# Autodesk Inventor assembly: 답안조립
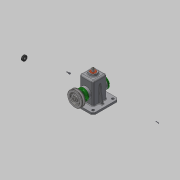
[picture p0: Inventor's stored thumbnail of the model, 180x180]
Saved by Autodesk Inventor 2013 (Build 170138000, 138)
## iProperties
Created: 2016-02
Part Number: 답안조립
Document SubType Name: Assembly
Designer: dgall
Author: dgall
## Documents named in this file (16)
- C:\Users\dgall\Desktop\460211V1003\답안조립.iam
- C:\Users\dgall\Desktop\460211V1003\V벨트풀리.ipt
- C:\Users\dgall\Desktop\460211V1003\고정핀 1.2 x 10.ipt
- C:\Users\dgall\Desktop\460211V1003\뒤커버.ipt
- C:\Users\dgall\Desktop\460211V1003\링크.ipt
- C:\Users\dgall\Desktop\460211V1003\멈춤나사 M3x8.ipt
- C:\Users\dgall\Desktop\460211V1003\베어링 12 x 32 x 10.ipt
- C:\Users\dgall\Desktop\460211V1003\본체.ipt
- C:\Users\dgall\Desktop\460211V1003\볼트 M4 x 12.ipt
- C:\Users\dgall\Desktop\460211V1003\부시.ipt
- C:\Users\dgall\Desktop\460211V1003\슬라이드.ipt
- C:\Users\dgall\Desktop\460211V1003\앞커버.ipt
- C:\Users\dgall\Desktop\460211V1003\오일실 12 25 7.ipt
- C:\Users\dgall\Desktop\460211V1003\키 4 x 4 x 10.ipt
- C:\Users\dgall\Desktop\460211V1003\편심축.ipt
- C:\Users\dgall\Desktop\460211V1003\핀 5 x 18.ipt
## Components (4 placed, 4 different names)
1. V벨트풀리:1
2. 고정핀 1.2 x 10:1
3. ISO 4762 M4 x 12:1
4. 핀 5 x 18:1
